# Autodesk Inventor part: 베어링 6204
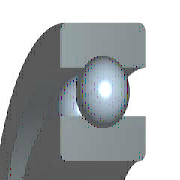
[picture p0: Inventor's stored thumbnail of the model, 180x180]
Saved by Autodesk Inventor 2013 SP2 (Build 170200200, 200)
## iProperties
IsCustomPart: 0
Created: 2015-12
Part Number: 베어링 6204
Material: 강철, 연강
Description: 깊은 그루브 볼 베어링
Document SubType Name: Modeling
Standard: KS B 2023
Designer: mdu
Standards Organization: KS
Language: ko-KR
Size Designation: 6204 - 20 x 47 x 14
Categories: <MemberInstance><Categories><Category DisplayName="샤프트 부품" InternalName="7f7aeb1f-a693-4053-b835-cee3144e0d98" Mnemonic="SHFT"><Category DisplayName="베어링" Inter
Density: 7.86 g/cm^3
Mass: 104.255 g
Surface Area: 87.8912 cm^2
Volume: 13.264 cm^3
Author: mud
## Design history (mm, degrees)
sketch "스케치" dims "d0" = 7.02 (= -0.26 x WD + 0.26 x BD)
  geometry: L1 (3.49, 16.75)-(10.51, 16.75); L2 (7, 16.75)-(7, 13.24); L3 (7, 16.75)-(7, 20.26); L4 (4.392, 14.401)-(0, 14.401); L5 (0, 10)-(14, 10); L6 (4.392, 19.099)-(0, 19.099); L7 (0, 23.5)-(14, 23.5); L8 (14, 10)-(14, 14.401); L9 (9.608, 14.401)-(14, 14.401); L10 (9.608, 19.099)-(14, 19.099); L11 (14, 23.5)-(14, 19.099); L12 (-1.4, 0)-(8.4, 0) reference; L13 (0, -0.3)-(0, 5.3) reference
  constraints: 22 end point, 4 point on line, 2 collinear, 2 perpendicular, 2 symmetric about line, 1 midpoint, 1 parallel, 14 other
  dimensions: "d9" = 20 diameter of L5 L12 (= WD); "d11" = 47 diameter of L7 L12 (= BD); "d12" = 14 distance between parallel lines of L8 L13 (= KB); "d13" = 28.802 diameter of L9 L12 (= 0.326 x BD + 0.674 x WD)
revolve "본체" stored, may be unused: angle "d6" = 90 deg
revolve "볼" stored, may be unused: angle "d7" = 90 deg
pattern_circular "IDS_ARRAYBALL[SIMPL:T]" dims angle "d3" = 360 deg
body "Solid1"
fillet "모깎기1" dims "d1" = 1 (= KRS)
other parameters: "WD" = 20 [user parameter; used in 5 equation terms], "BD" = 47 [user parameter; used in 5 equation terms], "KB" = 14 [user parameter; used in 1 equation term], "KRS" = 1 [user parameter; used in 1 equation term], "d4" = 0, "d5" = 0, "d8" = 0, "d14" = 0, "d15" = 0, "BBA" = 0 [user parameter], "BC0" = 6550000 [user parameter], "BC" = 1.27e+07 [user parameter], "BR" = 23.5 (= 0.5 x BD) [user parameter]
